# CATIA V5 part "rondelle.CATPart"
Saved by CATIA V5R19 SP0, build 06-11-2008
Part number: rondelle
Bounding box of the stored display mesh (mm): x 0 to 2.876, y -10 to 10, z -9.511 to 9.511
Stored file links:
  G:\project guitar elect\rondelle.CATPart
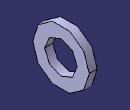
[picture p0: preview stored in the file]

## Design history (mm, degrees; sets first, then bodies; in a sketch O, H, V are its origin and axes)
Body1 (main body)
  Sketch1 on yz-plane, origin (0, 0, 0), H (0, 1, 0), V (0, 0, 1)
    circle A1 centre (0, 0) radius 5.75
    circle A2 centre (0, 0) radius 10
    radius A1 = 5.75
    radius A2 = 10
  Pad1: profile Sketch1, direction (1, 0, 0), length 2.876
